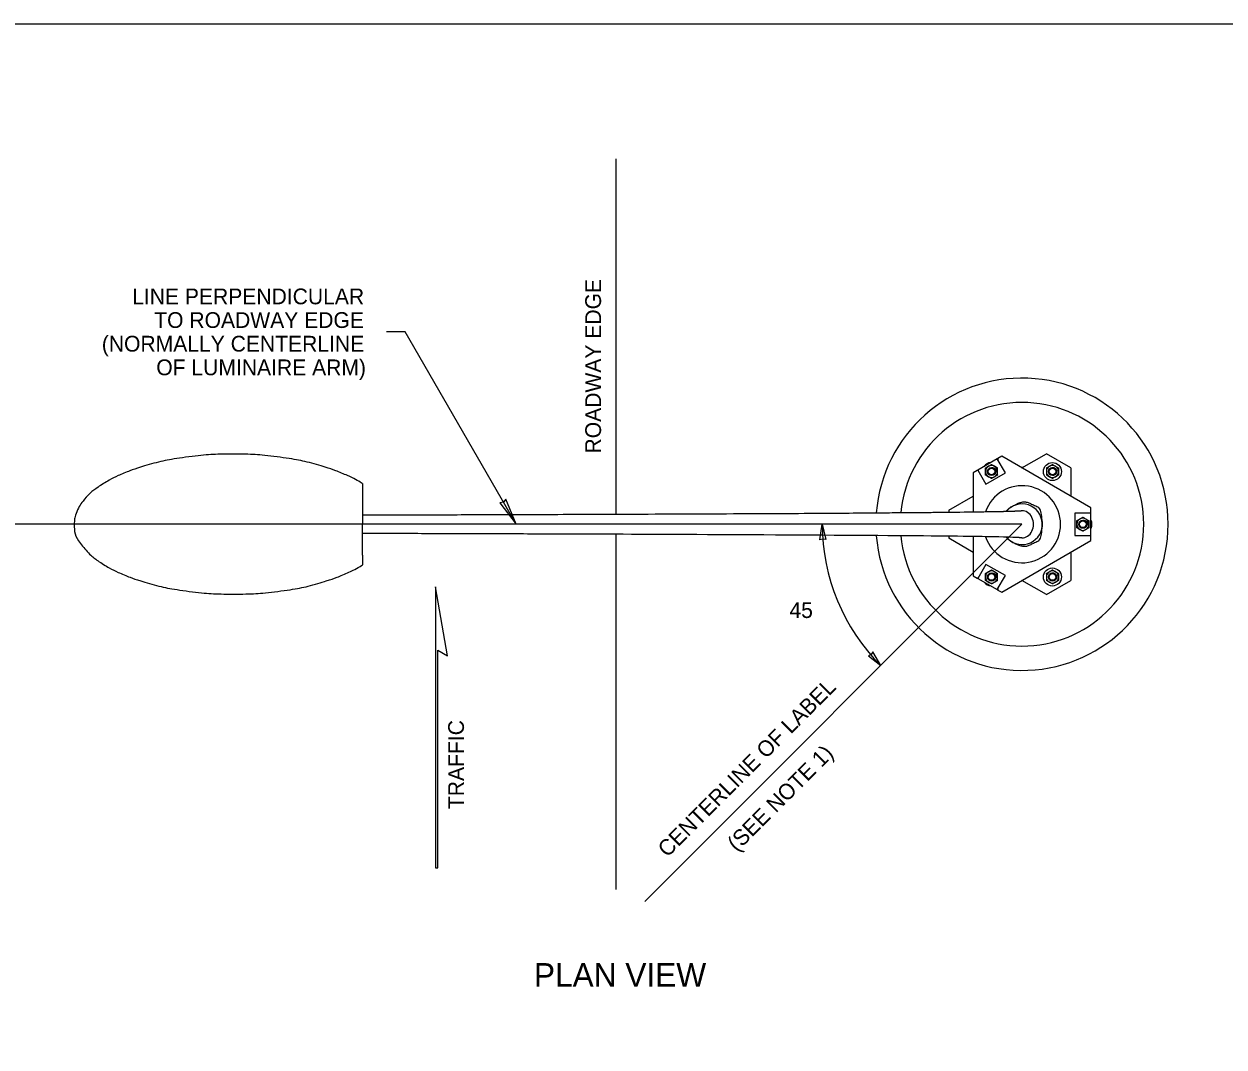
# Model space of a CAD drawing. Extents: x 99862 to 103680, y 99470 to 102076.
# Drawn here: x 100829 to 102047, y 101038 to 102076 of the extents above; entities that cross this region are included whole.
import ezdxf

# ---------------------------------------------------------------- set-up
doc = ezdxf.new("R2010")
doc.units = 0
for name, color, linetype in [('Level 1', 7, 'Continuous'), ('Level 11', 7, 'Continuous'), ('Level 12', 7, 'Continuous'), ('Level 15', 7, 'Continuous'), ('Level 18', 7, 'Continuous'), ('Level 19', 7, 'Continuous'), ('Level 20', 7, 'Continuous'), ('Level 3', 7, 'Continuous'), ('Level 44', 7, 'Continuous'), ('Level 5', 7, 'Continuous'), ('Level 62', 7, 'Continuous'), ('Level 7', 7, 'Continuous'), ('Level 9', 7, 'Continuous')]:
    doc.layers.add(name, color=color, linetype=linetype)

msp = doc.modelspace()

# ---------------------------------------------------------------- linework, layer by layer
at = {"layer": 'Level 1'}
msp.add_lwpolyline([(99862, 99999.5), (103151, 99999.5), (103151, 102075.5), (99862, 102075.5)], close=True, dxfattribs=at)
at = {"layer": 'Level 11'}
for p, q in [((101817, 101634.2), (101797.4, 101622.9)), ((101825.3, 101620), (101817, 101634.2)), ((101797.4, 101622.9), (101805.6, 101608.6)), ((101805.6, 101608.6), (101825.3, 101620)), ((101895.8, 101579.3), (101895.8, 101556.6)), ((101912.2, 101579.3), (101895.8, 101579.3)), ((101912.2, 101556.6), (101912.2, 101579.3)), ((101895.8, 101556.6), (101912.2, 101556.6)), ((101805.6, 101527.2), (101797.4, 101513)), ((101825.3, 101515.9), (101805.6, 101527.2)), ((101797.4, 101513), (101817, 101501.6)), ((101817, 101501.6), (101825.3, 101515.9))]:
    msp.add_line(p, q, dxfattribs=at)
at = {"layer": 'Level 12'}
msp.add_line((101843.2, 101625.6), (101841.2, 101625.6), dxfattribs=at)
for radius, start, end in [(148.3, 184.4932, 175.5067), (123.6, 185.4842, 174.5158)]:
    msp.add_arc((101842.2, 101567.9), radius, start, end, dxfattribs=at)
at = {"layer": 'Level 15'}
for p, q in [((101216.3, 101763.1), (101197.2, 101763.1)), ((101328.9, 101567.9), (101216.3, 101763.1)), ((101842.2, 101567.9), (100759.6, 101567.9)), ((101842.2, 101567.9), (101459.5, 101185.2))]:
    msp.add_line(p, q, dxfattribs=at)
for points in [[(101328.9, 101567.9), (101318.4, 101593.3), (101316, 101590.4), (101312.2, 101589.7)], [(101639.5, 101567.9), (101643.2, 101552.3), (101640.1, 101552.9), (101637.1, 101552.1)], [(101698.9, 101424.6), (101690.9, 101438.5), (101689.1, 101435.9), (101686.3, 101434.5)]]:
    msp.add_lwpolyline(points, close=True, dxfattribs=at)
msp.add_arc((101842.2, 101567.9), 202.7, 180, 225, dxfattribs=at)
at = {"layer": 'Level 18'}
for radius, start, end in [(39.1, 199.0265, 160.9736), (20.6, 226.3698, 140.2341), (20.6, 219.7597, 226.3698)]:
    msp.add_arc((101842.2, 101567.9), radius, start, end, dxfattribs=at)
at = {"layer": 'Level 19'}
msp.add_ellipse((101842.3, 101567.9), major_axis=(0, -13.8), ratio=0.83583, start_param=6.262626, end_param=9.445347, dxfattribs=at)
for points, degree in [([(101826.4, 101581.1), (101827.6, 101582.5), (101828.9, 101583.8), (101830.3, 101584.8), (101831.9, 101585.8), (101831.9, 101585.8), (101831.9, 101585.8), (101831.9, 101585.8), (101831.9, 101585.8), (101847.4, 101594.7), (101852.5, 101585.8), (101862.8, 101585.8), (101862.8, 101567.9)], 4), ([(101173, 101577.4), (101173.7, 101577.4), (101178.1, 101577.4), (101184, 101577.4), (101189.8, 101577.4), (101192.8, 101577.4), (101195, 101577.4), (101219, 101577.5), (101255.4, 101577.6), (101291.8, 101577.7), (101306.3, 101577.7), (101308.6, 101577.8), (101318.8, 101577.8), (101328.9, 101577.8), (101339, 101577.8), (101341.4, 101577.9), (101343.7, 101577.9), (101346.1, 101577.9), (101348.4, 101577.9), (101350.8, 101577.9), (101353.1, 101577.9), (101375.4, 101578), (101491.8, 101578.4), (101608.6, 101578.9), (101692.5, 101579.5), (101709.2, 101579.7), (101717.3, 101579.7), (101718.9, 101579.7), (101720.5, 101579.8), (101722, 101579.8), (101723.6, 101579.8), (101725.2, 101579.8), (101726.7, 101579.8), (101728.3, 101579.8), (101729.8, 101579.8), (101743.4, 101579.9), (101756, 101580.1), (101781.2, 101580.3), (101794.3, 101580.5), (101805.2, 101580.7), (101806, 101580.7), (101806.9, 101580.7), (101807.8, 101580.7), (101808.6, 101580.7), (101809.5, 101580.8), (101811.7, 101580.8), (101816.2, 101580.9), (101820.3, 101581), (101822.9, 101581), (101823.5, 101581), (101824.2, 101581.1), (101825, 101581.1), (101826, 101581.1), (101828.9, 101581.2), (101831.4, 101581.2), (101833.3, 101581.3), (101833.8, 101581.3), (101834.2, 101581.3), (101834.6, 101581.3), (101835, 101581.4), (101835.4, 101581.4), (101835.8, 101581.4), (101836.2, 101581.4), (101836.6, 101581.4), (101837, 101581.4), (101837.3, 101581.4), (101837.6, 101581.5), (101837.9, 101581.5), (101838.2, 101581.5), (101838.4, 101581.5), (101838.6, 101581.5), (101838.9, 101581.5), (101839.2, 101581.5), (101839.5, 101581.6), (101839.7, 101581.6), (101840, 101581.6), (101840.2, 101581.6), (101840.4, 101581.6), (101840.7, 101581.6), (101840.9, 101581.6), (101841.1, 101581.6), (101841.2, 101581.7), (101841.4, 101581.7), (101841.6, 101581.7), (101841.7, 101581.7), (101841.8, 101581.7), (101841.9, 101581.7), (101842, 101581.7), (101842.1, 101581.7), (101842.1, 101581.7), (101842.1, 101581.7), (101842.1, 101581.7)], 3), ([(101862.8, 101567.9), (101862.8, 101550.1), (101852.5, 101550.1), (101847.4, 101541.2), (101831.9, 101550.1), (101831.9, 101550.1), (101831.9, 101550.1), (101831.9, 101550.1), (101831.9, 101550.1), (101830.3, 101551), (101828.9, 101552.1), (101827.6, 101553.3), (101826.4, 101554.8)], 4), ([(101842.1, 101554.1), (101842.1, 101554.1), (101841.8, 101554.2), (101841.2, 101554.2), (101841.1, 101554.2), (101840.9, 101554.2), (101840.7, 101554.2), (101840.4, 101554.3), (101840.2, 101554.3), (101840, 101554.3), (101839.7, 101554.3), (101839.4, 101554.3), (101824.9, 101555.1), (101737.2, 101556.2), (101521.1, 101557.4), (101381.9, 101557.9), (101311, 101558.1), (101290.6, 101558.2), (101270.1, 101558.2), (101249.7, 101558.3), (101223.4, 101558.4), (101197.8, 101558.4), (101173, 101558.5)], 3)]:
    msp.add_open_spline(points, degree=degree, dxfattribs=at)
at = {"layer": 'Level 3'}
for p, q in [((101842.2, 101625), (101866.9, 101639.3)), ((101891.6, 101625), (101866.9, 101639.3)), ((101891.6, 101625), (101891.6, 101596.5)), ((101768.1, 101582.2), (101792.8, 101596.5)), ((101768.1, 101582.2), (101768.1, 101580.2)), ((101768.1, 101555.7), (101768.1, 101553.7)), ((101792.8, 101539.4), (101768.1, 101553.7)), ((101891.6, 101539.4), (101891.6, 101510.9)), ((101866.9, 101496.6), (101842.2, 101510.9)), ((101866.9, 101496.6), (101891.6, 101510.9))]:
    msp.add_line(p, q, dxfattribs=at)
msp.add_lwpolyline([(101249.4, 101219.3), (101249.4, 101440), (101259.3, 101434.3), (101246.9, 101504.3), (101246.9, 101219.3)], close=True, dxfattribs=at)
for points, degree in [([(101172.9, 101609.2), (101172.9, 101609.3), (101172.8, 101609.3), (101166, 101613.5), (101158.9, 101616.9), (101144.6, 101622.8), (101137.4, 101625.3), (101115.6, 101631.6), (101101, 101634.4), (101071.4, 101638.2), (101056.5, 101639.1), (101026.4, 101639.1), (101011.5, 101638.2), (100981.9, 101634.4), (100967.2, 101631.6), (100945.3, 101625.2), (100938, 101622.7), (100923.8, 101616.8), (100916.9, 101613.4), (100903.4, 101605), (100896.8, 101600.1), (100888.4, 101590.4), (100885.8, 101586.8), (100881.8, 101578.2), (100880.5, 101573.4), (100880.5, 101568.3), (100880.5, 101558), (100885.6, 101549.2), (100896.8, 101536.4), (100903.4, 101531.3), (100917, 101522.9), (100923.9, 101519.5), (100938.2, 101513.5), (100945.5, 101511), (100967.5, 101504.6), (100982.3, 101501.7), (101012, 101497.9), (101026.9, 101497), (101057.1, 101497), (101072.1, 101497.9), (101101.9, 101501.7), (101116.7, 101504.5), (101138.7, 101511), (101146, 101513.5), (101159.9, 101519.4), (101166.5, 101522.6), (101172.9, 101526.6)], 3), ([(101172.9, 101609.2), (101172.9, 101608.4), (101172.9, 101607.6), (101172.9, 101606.8), (101172.9, 101606), (101172.9, 101605.1), (101172.9, 101604.3), (101172.9, 101602.7), (101172.9, 101601), (101172.9, 101599.4)], 3), ([(101172.9, 101599.4), (101172.9, 101599.4), (101172.9, 101596.3), (101172.9, 101584), (101172.9, 101575.3), (101172.9, 101567.9)], 3), ([(101172.9, 101536.4), (101172.9, 101536.4), (101172.9, 101567.9)], 2), ([(101172.9, 101536.4), (101172.9, 101534.8), (101172.9, 101533.1), (101172.9, 101531.5), (101172.9, 101530.7), (101172.9, 101529.8), (101172.9, 101529), (101172.9, 101528.2), (101172.9, 101527.4), (101172.9, 101526.6)], 3)]:
    msp.add_open_spline(points, degree=degree, dxfattribs=at)
at = {"layer": 'Level 44'}
for p, q in [((101430, 101938.6), (101430, 101578)), ((101430, 101557.9), (101430, 101197.2))]:
    msp.add_line(p, q, dxfattribs=at)
at = {"layer": 'Level 5'}
for p, q in [((101817.7, 101634.6), (101817, 101634.2)), ((101797.4, 101622.9), (101796.7, 101622.5)), ((101912.2, 101579.3), (101912.2, 101580)), ((101912.2, 101555.8), (101912.2, 101556.6)), ((101797.4, 101513), (101796.7, 101513.3)), ((101817.7, 101501.2), (101817, 101501.6))]:
    msp.add_line(p, q, dxfattribs=at)
at = {"layer": 'Level 62'}
for points, degree in [([(101808.9, 101624.8), (101809.1, 101624.9), (101809.3, 101625), (101809.5, 101625.1)], 3), ([(101811.7, 101625.5), (101815, 101625.2), (101816.5, 101622.3), (101815, 101619.5), (101814.7, 101619), (101814.4, 101618.6), (101813.9, 101618.3)], 4), ([(101872.4, 101625.5), (101873.9, 101625.8), (101875.2, 101625.3), (101876.1, 101624.3), (101877, 101623.4), (101877.4, 101622.1), (101877.2, 101620.7)], 4), ([(101876.7, 101619.4), (101876.1, 101618.3), (101875.1, 101617.7), (101874.1, 101617.4), (101873.8, 101617.4), (101873.6, 101617.3), (101873.4, 101617.3)], 4), ([(101901.6, 101571.3), (101901.8, 101571.4), (101902, 101571.5), (101902.2, 101571.6)], 3), ([(101904.4, 101572), (101907.7, 101571.7), (101909.2, 101568.8), (101907.6, 101566), (101907.4, 101565.5), (101907, 101565.1), (101906.6, 101564.7)], 4), ([(101808.9, 101517.8), (101809.1, 101517.9), (101809.3, 101518), (101809.5, 101518.1)], 3), ([(101811.7, 101518.5), (101815, 101518.2), (101816.5, 101515.3), (101815, 101512.5), (101814.7, 101512), (101814.4, 101511.6), (101813.9, 101511.2)], 4), ([(101872.4, 101518.5), (101873.9, 101518.7), (101875.2, 101518.2), (101876.1, 101517.3), (101877, 101516.4), (101877.4, 101515.1), (101877.2, 101513.7)], 4), ([(101876.7, 101512.4), (101876.1, 101511.3), (101875.1, 101510.7), (101874.1, 101510.4), (101873.8, 101510.4), (101873.6, 101510.3), (101873.4, 101510.3)], 4)]:
    msp.add_open_spline(points, degree=degree, dxfattribs=at)
at = {"layer": 'Level 7'}
for p, q in [((101817.7, 101634.6), (101817.6, 101633.3)), ((101821.6, 101636.9), (101817.7, 101634.6)), ((101912.2, 101584.6), (101821.6, 101636.9)), ((101796.7, 101622.5), (101792.8, 101620.2)), ((101798, 101622), (101796.7, 101622.5)), ((101792.8, 101620.2), (101792.8, 101580.5)), ((101912.2, 101580), (101912.2, 101584.6)), ((101911.1, 101579.3), (101912.2, 101580)), ((101792.8, 101555.4), (101792.8, 101515.6)), ((101821.6, 101499), (101912.2, 101551.3)), ((101912.2, 101555.8), (101911.1, 101556.6)), ((101912.2, 101551.3), (101912.2, 101555.8)), ((101792.8, 101515.6), (101796.7, 101513.3)), ((101796.7, 101513.3), (101798, 101513.9)), ((101817.6, 101502.6), (101817.7, 101501.2)), ((101817.7, 101501.2), (101821.6, 101499))]:
    msp.add_line(p, q, dxfattribs=at)
at = {"layer": 'Level 9'}
for p, q in [((101805.2, 101621.3), (101805.2, 101621.6)), ((101808.2, 101626.7), (101808.3, 101626.8)), ((101869.9, 101626.7), (101870.1, 101626.8)), ((101876.1, 101626.9), (101876.3, 101626.7)), ((101879.3, 101621.6), (101879.3, 101621.3)), ((101808.4, 101616), (101808.1, 101616.2)), ((101814.5, 101616.2), (101814.3, 101616)), ((101876.3, 101616.1), (101876.1, 101616)), ((101900.8, 101573.2), (101901, 101573.3)), ((101897.8, 101567.8), (101897.8, 101568.1)), ((101901.1, 101562.5), (101900.8, 101562.7)), ((101907.2, 101562.6), (101907, 101562.5)), ((101805.2, 101514.3), (101805.2, 101514.6)), ((101808.2, 101519.7), (101808.3, 101519.8)), ((101869.9, 101519.7), (101870.1, 101519.8)), ((101876.1, 101519.9), (101876.3, 101519.7)), ((101879.3, 101514.6), (101879.3, 101514.3)), ((101808.4, 101509), (101808.1, 101509.2)), ((101814.5, 101509.1), (101814.3, 101509)), ((101876.3, 101509.1), (101876.1, 101509))]:
    msp.add_line(p, q, dxfattribs=at)
for centre, radius in [((101811.3, 101621.4), 4.12), ((101811.3, 101621.4), 3.39), ((101873.1, 101621.4), 9.15), ((101873.1, 101621.4), 4.12), ((101873.1, 101621.4), 3.39), ((101904, 101567.9), 4.12), ((101904, 101567.9), 3.39), ((101873.1, 101514.4), 9.15), ((101811.3, 101514.4), 4.12), ((101811.3, 101514.4), 3.39), ((101873.1, 101514.4), 4.12), ((101873.1, 101514.4), 3.39)]:
    msp.add_circle(centre, radius, dxfattribs=at)
for centre, radius, start, end in [((101811.3, 101621.4), 9.15, 94.1581, 145.8419), ((101811.3, 101621.4), 6.18, 120.758, 178.5832), ((101811.3, 101621.4), 6.18, 181.4168, 238.4392), ((101811.3, 101621.4), 6.18, 0, 119.2446), ((101811.3, 101621.4), 6.18, 301.1969, 0), ((101873.1, 101621.4), 6.18, 121.1969, 180), ((101873.1, 101621.4), 6.18, 180, 299.2446), ((101873.1, 101621.4), 6.18, 61.5608, 118.8031), ((101873.1, 101621.4), 6.18, 1.4168, 58.4392), ((101873.1, 101621.4), 6.18, 300.758, 358.5832), ((101811.3, 101621.4), 6.18, 241.5608, 298.8031), ((101904, 101567.9), 6.18, 120.758, 178.5832), ((101904, 101567.9), 6.18, 360, 119.2446), ((101904, 101567.9), 6.18, 181.4168, 238.4392), ((101904, 101567.9), 6.18, 241.5608, 298.8031), ((101904, 101567.9), 6.18, 301.1969, 0), ((101904, 101567.9), 9.15, 334.1581, 25.8419), ((101811.3, 101514.4), 6.18, 120.758, 178.5832), ((101811.3, 101514.4), 6.18, 181.4168, 238.4392), ((101811.3, 101514.4), 6.18, 0, 119.2446), ((101811.3, 101514.4), 6.18, 301.1969, 360), ((101873.1, 101514.4), 6.18, 121.1969, 180), ((101873.1, 101514.4), 6.18, 180, 299.2446), ((101873.1, 101514.4), 6.18, 61.5608, 118.8031), ((101873.1, 101514.4), 6.18, 1.4168, 58.4392), ((101873.1, 101514.4), 6.18, 300.758, 358.5832), ((101811.3, 101514.4), 9.15, 214.1581, 265.8419), ((101811.3, 101514.4), 6.18, 241.5608, 298.8031)]:
    msp.add_arc(centre, radius, start, end, dxfattribs=at)
for points, degree in [([(101805.2, 101625), (101806.1, 101625.6), (101807.1, 101626.2), (101808.2, 101626.7)], 2), ([(101805.2, 101621.6), (101805.2, 101622.2), (101805.2, 101622.8), (101805.2, 101623.9), (101805.2, 101624.5), (101805.2, 101625)], 3), ([(101805.2, 101617.9), (101805.2, 101619), (101805.2, 101620.1), (101805.2, 101621.3)], 2), ([(101808.3, 101626.8), (101809.3, 101627.4), (101810.3, 101628), (101811.3, 101628.6)], 2), ([(101811.3, 101628.6), (101812.3, 101628), (101813.4, 101627.4), (101815.5, 101626.2), (101816.5, 101625.6), (101817.5, 101625)], 3), ([(101817.5, 101621.4), (101817.5, 101622), (101817.5, 101622.7), (101817.5, 101623.8), (101817.5, 101624.4), (101817.5, 101625)], 3), ([(101817.5, 101617.9), (101817.5, 101619), (101817.5, 101620.2), (101817.5, 101621.4)], 2), ([(101866.9, 101625), (101867.9, 101625.6), (101868.9, 101626.1), (101869.9, 101626.7)], 2), ([(101866.9, 101625), (101866.9, 101623.8), (101866.9, 101622.6), (101866.9, 101621.4)], 2), ([(101866.9, 101621.4), (101866.9, 101620.8), (101866.9, 101620.2), (101866.9, 101619), (101866.9, 101618.4), (101866.9, 101617.9)], 3), ([(101870.1, 101626.8), (101871.1, 101627.4), (101872.1, 101628), (101873.1, 101628.6)], 2), ([(101873.1, 101628.6), (101874.1, 101628), (101875.1, 101627.4), (101876.1, 101626.9)], 2), ([(101876.3, 101626.7), (101877.3, 101626.1), (101878.3, 101625.6), (101879.3, 101625)], 2), ([(101879.3, 101625), (101879.3, 101623.9), (101879.3, 101622.7), (101879.3, 101621.6)], 2), ([(101879.3, 101621.3), (101879.3, 101620.7), (101879.3, 101620.1), (101879.3, 101619), (101879.3, 101618.4), (101879.3, 101617.9)], 3), ([(101808.1, 101616.2), (101807.1, 101616.8), (101806.1, 101617.3), (101805.2, 101617.9)], 2), ([(101811.3, 101614.3), (101810.4, 101614.9), (101809.4, 101615.4), (101808.4, 101616)], 2), ([(101814.3, 101616), (101813.3, 101615.4), (101812.3, 101614.9), (101811.3, 101614.3)], 2), ([(101817.5, 101617.9), (101816.5, 101617.3), (101815.5, 101616.7), (101814.5, 101616.2)], 2), ([(101873.1, 101614.3), (101872.1, 101614.9), (101871.1, 101615.5), (101869, 101616.7), (101867.9, 101617.3), (101866.9, 101617.9)], 3), ([(101876.1, 101616), (101875.1, 101615.5), (101874.1, 101614.9), (101873.1, 101614.3)], 2), ([(101879.3, 101617.9), (101878.3, 101617.3), (101877.3, 101616.7), (101876.3, 101616.1)], 2), ([(101897.8, 101571.5), (101898.8, 101572.1), (101899.8, 101572.6), (101900.8, 101573.2)], 2), ([(101901, 101573.3), (101902, 101573.9), (101903, 101574.5), (101904, 101575.1)], 2), ([(101904, 101575.1), (101905, 101574.5), (101906, 101573.9), (101908.1, 101572.7), (101909.2, 101572.1), (101910.2, 101571.5)], 3), ([(101897.8, 101568.1), (101897.8, 101568.7), (101897.8, 101569.2), (101897.8, 101570.4), (101897.8, 101570.9), (101897.8, 101571.5)], 3), ([(101897.8, 101564.4), (101897.8, 101565.5), (101897.8, 101566.6), (101897.8, 101567.8)], 2), ([(101900.8, 101562.7), (101899.8, 101563.2), (101898.8, 101563.8), (101897.8, 101564.4)], 2), ([(101904, 101560.8), (101903, 101561.4), (101902.1, 101561.9), (101901.1, 101562.5)], 2), ([(101907, 101562.5), (101906, 101561.9), (101905, 101561.4), (101904, 101560.8)], 2), ([(101910.2, 101564.4), (101909.2, 101563.8), (101908.2, 101563.2), (101907.2, 101562.6)], 2), ([(101910.2, 101567.9), (101910.2, 101568.5), (101910.2, 101569.1), (101910.2, 101570.3), (101910.2, 101570.9), (101910.2, 101571.5)], 3), ([(101910.2, 101564.4), (101910.2, 101565.5), (101910.2, 101566.7), (101910.2, 101567.9)], 2), ([(101805.2, 101518), (101806.1, 101518.6), (101807.1, 101519.1), (101808.2, 101519.7)], 2), ([(101805.2, 101514.6), (101805.2, 101515.2), (101805.2, 101515.7), (101805.2, 101516.9), (101805.2, 101517.4), (101805.2, 101518)], 3), ([(101805.2, 101510.9), (101805.2, 101512), (101805.2, 101513.1), (101805.2, 101514.3)], 2), ([(101808.3, 101519.8), (101809.3, 101520.4), (101810.3, 101521), (101811.3, 101521.6)], 2), ([(101811.3, 101521.6), (101812.3, 101521), (101813.4, 101520.4), (101815.5, 101519.2), (101816.5, 101518.6), (101817.5, 101518)], 3), ([(101817.5, 101514.4), (101817.5, 101515), (101817.5, 101515.6), (101817.5, 101516.8), (101817.5, 101517.4), (101817.5, 101518)], 3), ([(101817.5, 101510.9), (101817.5, 101512), (101817.5, 101513.2), (101817.5, 101514.4)], 2), ([(101866.9, 101518), (101867.9, 101518.6), (101868.9, 101519.1), (101869.9, 101519.7)], 2), ([(101866.9, 101518), (101866.9, 101516.8), (101866.9, 101515.6), (101866.9, 101514.4)], 2), ([(101866.9, 101514.4), (101866.9, 101513.8), (101866.9, 101513.2), (101866.9, 101512), (101866.9, 101511.4), (101866.9, 101510.9)], 3), ([(101870.1, 101519.8), (101871.1, 101520.4), (101872.1, 101521), (101873.1, 101521.6)], 2), ([(101873.1, 101521.6), (101874.1, 101521), (101875.1, 101520.4), (101876.1, 101519.9)], 2), ([(101876.3, 101519.7), (101877.3, 101519.1), (101878.3, 101518.5), (101879.3, 101518)], 2), ([(101879.3, 101518), (101879.3, 101516.9), (101879.3, 101515.7), (101879.3, 101514.6)], 2), ([(101879.3, 101514.3), (101879.3, 101513.7), (101879.3, 101513.1), (101879.3, 101512), (101879.3, 101511.4), (101879.3, 101510.9)], 3), ([(101808.1, 101509.2), (101807.1, 101509.7), (101806.1, 101510.3), (101805.2, 101510.9)], 2), ([(101811.3, 101507.3), (101810.4, 101507.9), (101809.4, 101508.4), (101808.4, 101509)], 2), ([(101814.3, 101509), (101813.3, 101508.4), (101812.3, 101507.9), (101811.3, 101507.3)], 2), ([(101817.5, 101510.9), (101816.5, 101510.3), (101815.5, 101509.7), (101814.5, 101509.1)], 2), ([(101873.1, 101507.3), (101872.1, 101507.9), (101871.1, 101508.5), (101869, 101509.7), (101867.9, 101510.3), (101866.9, 101510.9)], 3), ([(101876.1, 101509), (101875.1, 101508.4), (101874.1, 101507.9), (101873.1, 101507.3)], 2), ([(101879.3, 101510.9), (101878.3, 101510.3), (101877.3, 101509.7), (101876.3, 101509.1)], 2)]:
    msp.add_open_spline(points, degree=degree, dxfattribs=at)

# ---------------------------------------------------------------- texts
at = {"layer": 'Level 20'}
for s, rotation, p in [('ROADWAY EDGE', 90, (101415, 101639.7)), ('CENTERLINE OF LABEL', 45, (101482.3, 101229.2)), ('TRAFFIC', 90, (101275.9, 101278.9)), ('(SEE NOTE 1)', 45, (101552.9, 101234.8))]:
    msp.add_text(s, height=16, rotation=rotation, dxfattribs=at).set_placement(p)
for s, height, p in [('LINE PERPENDICULAR', 16, (100939.2, 101791.1)), ('TO ROADWAY EDGE', 16, (100961.6, 101767.1)), ('(NORMALLY CENTERLINE', 16, (100908.4, 101743.1)), ('OF LUMINAIRE ARM)', 16, (100963.7, 101719.1)), ('45', 16, (101606.2, 101472.8)), ('PLAN VIEW', 24, (101346.9, 101098.6))]:
    msp.add_text(s, height=height, dxfattribs=at).set_placement(p)

doc.saveas('drawing.dxf')
